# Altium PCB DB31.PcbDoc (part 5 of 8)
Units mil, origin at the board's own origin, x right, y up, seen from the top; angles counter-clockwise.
Board outline 3236.22 x 4456.69 mil, 8 copper layers (Top Layer, MidLayer1, MidLayer2, GND-Layer5, MidLayer3, VCC, MidLayer4, Bottom Layer), stack 61.8 mil thick; 226 components, 469 nets, 1815 pads, 1562 vias.
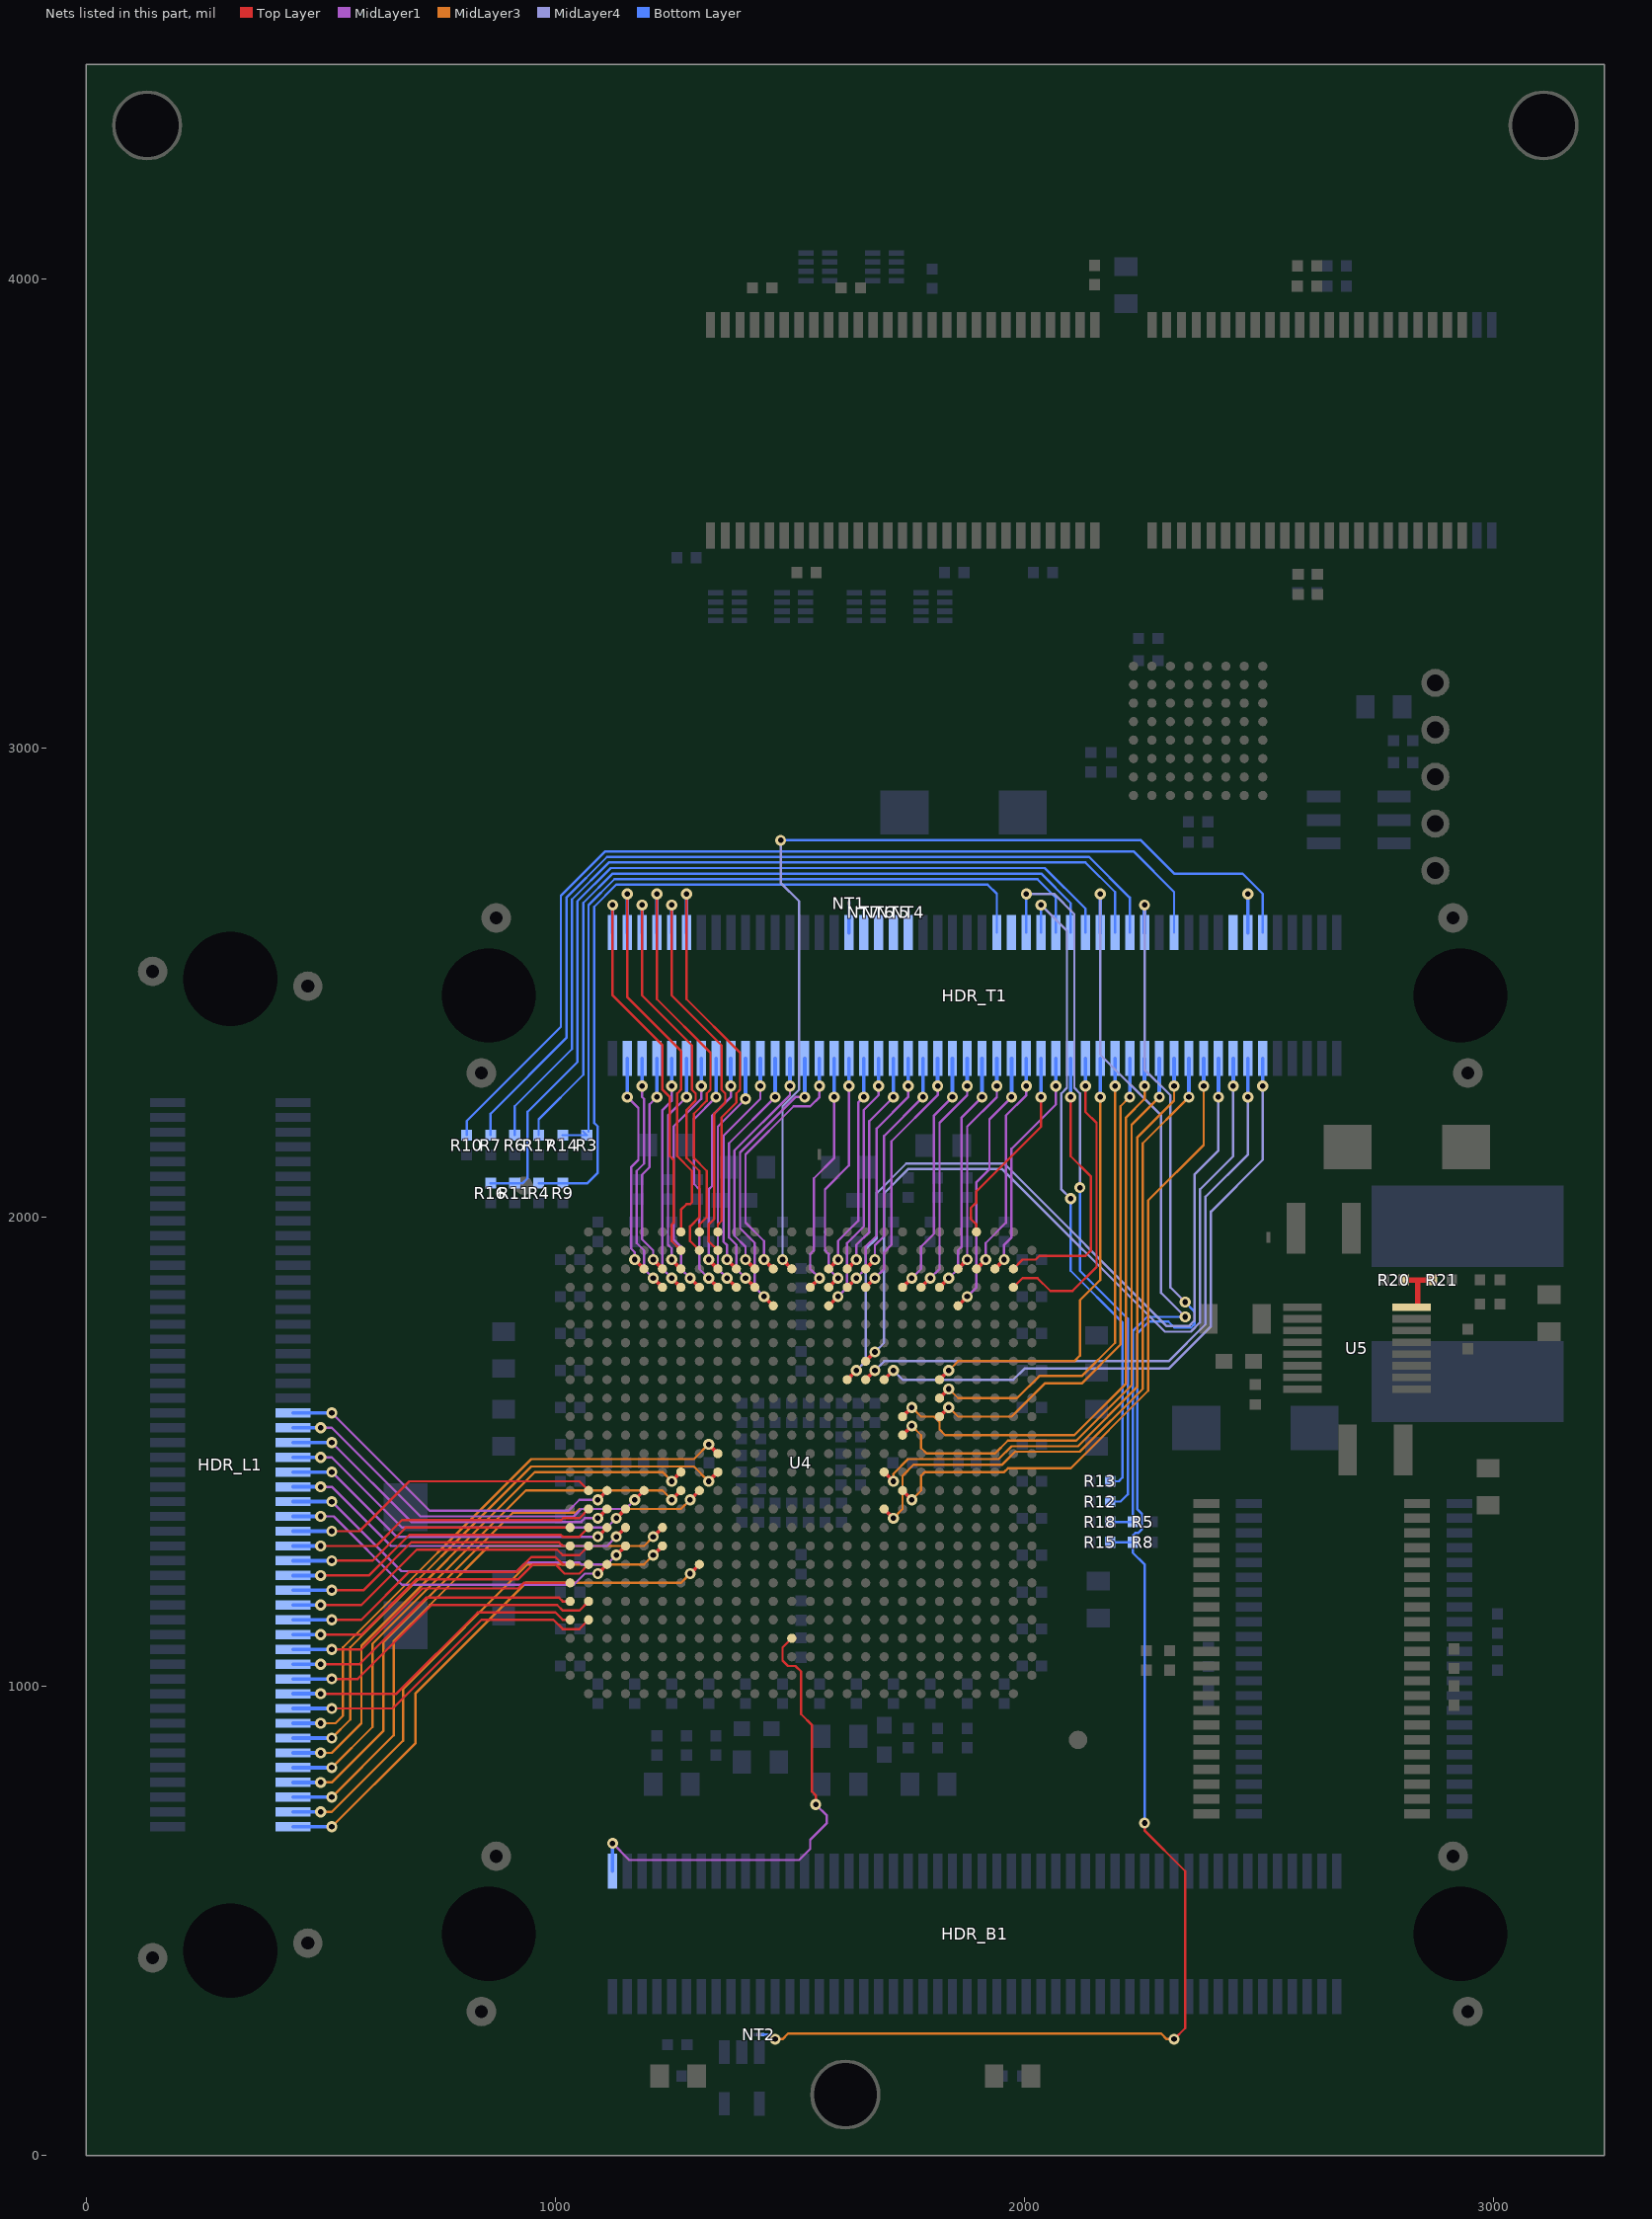
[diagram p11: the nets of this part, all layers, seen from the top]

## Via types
v1: diameter 23.62, hole 11.81, Top Layer to Bottom Layer, 947 vias
v2: diameter 23.62, hole 11.81, Top Layer to Bottom Layer, tented both sides, 476 vias
v3: diameter 27.56, hole 15.75, Top Layer to Bottom Layer, 138 vias
v4: diameter 23.62, hole 11.81, Top Layer to Bottom Layer, tented top, 1 vias

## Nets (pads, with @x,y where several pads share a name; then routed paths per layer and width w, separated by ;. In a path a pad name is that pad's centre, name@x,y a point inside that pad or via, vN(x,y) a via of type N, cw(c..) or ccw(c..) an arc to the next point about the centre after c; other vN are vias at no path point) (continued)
EXTEND_B21: HDR_L1.44 U4.R3 | length 773.7
  Top Layer w7.87: v1(1090.55,1397.64) U4.R3@1110.24,1417.32
  MidLayer1 w5: v2(523.62,1582.68) 732.28,1374.02 956.69,1374.02 968.5,1374.02 1027.56,1374.02 1051.18,1397.64 v1(1090.55,1397.64)
  Bottom Layer w7.87: HDR_L1.44@440.94,1582.67 v2(523.62,1582.68)
EXTEND_B22: HDR_L1.46 U4.R5 | length 849.1
  Top Layer w7.87: v1(1169.29,1397.64) U4.R5@1188.98,1417.32
  MidLayer1 w5: v2(500,1551.18) 523.62,1551.18 712.6,1362.2 956.69,1362.2 968.5,1362.2 1039.37,1362.2 1055.12,1377.95 1149.61,1377.95 v1(1169.29,1397.64)
  Bottom Layer w7.87: HDR_L1.46@440.94,1551.18 v2(500,1551.18)
EXTEND_B23: HDR_L1.48 U4.T3 | length 750.8
  Top Layer w7.87: v1(1090.55,1358.27) U4.T3@1110.24,1377.95
  MidLayer1 w5: v2(523.62,1519.68) 692.91,1350.39 956.69,1350.39 968.5,1350.39 1055.12,1350.39 1062.99,1358.27 v1(1090.55,1358.27)
  Bottom Layer w7.87: HDR_L1.48@440.94,1519.68 v2(523.62,1519.68)
EXTEND_B24: HDR_L1.50 U4.T4 | length 786.9
  Top Layer w7.87: v1(1129.92,1358.27) U4.T4@1149.61,1377.95
  MidLayer1 w5: v2(500,1488.19) 523.62,1488.19 673.23,1338.58 956.69,1338.58 968.5,1338.58 1110.24,1338.58 v1(1129.92,1358.27)
  Bottom Layer w7.87: HDR_L1.50@440.94,1488.19 v2(500,1488.19)
EXTEND_B25: HDR_L1.52 U4.U3 | length 734.5
  Top Layer w7.87: v1(1090.55,1318.9) U4.U3@1110.24,1338.58
  MidLayer1 w5: v2(523.62,1456.69) 661.42,1318.9 956.69,1318.9 968.5,1318.9 v1(1090.55,1318.9)
  Bottom Layer w7.87: HDR_L1.52@440.94,1456.69 v2(523.62,1456.69)
EXTEND_B26: HDR_L1.54 U4.U4 | length 777.2
  Top Layer w7.87: v1(1129.92,1318.9) U4.U4@1149.61,1338.58
  MidLayer1 w5: v2(500,1425.2) 523.62,1425.2 649.61,1299.21 956.69,1299.21 968.5,1299.21 1110.24,1299.21 v1(1129.92,1318.9)
  Bottom Layer w7.87: HDR_L1.54@440.94,1425.19 v2(500,1425.2)
EXTEND_B27: HDR_L1.56 U4.V4 | length 795.7
  Top Layer w7.87: v1(1129.92,1279.53) U4.V4@1149.61,1299.21
  MidLayer1 w5: v2(523.62,1393.7) 672,1245.32 918.55,1245.32 937.01,1263.78 956.69,1263.78 968.5,1263.78 1051.18,1263.78 1055.12,1259.84 1110.24,1259.84 v1(1129.92,1279.53)
  Bottom Layer w7.87: HDR_L1.56@440.94,1393.7 v2(523.62,1393.7)
EXTEND_B28: HDR_L1.58 U4.W3 | length 747.6
  Top Layer w7.87: v1(1090.55,1240.16) U4.W3@1110.24,1259.84
  MidLayer1 w5: v2(500,1362.21) 527.56,1362.21 673.23,1216.54 956.69,1216.54 968.5,1216.53 1039.37,1216.53 1062.99,1240.16 v1(1090.55,1240.16)
  Bottom Layer w7.87: HDR_L1.58@440.94,1362.2 v2(500,1362.21)
EXTEND_B29: HDR_L1.60 U4.R2 | length 682.1
  Top Layer w5: v2(523.62,1330.71) 582.68,1330.71 688.98,1437.01 956.69,1437.01 968.5,1437.01 1051.18,1437.01 U4.R2@1070.87,1417.32
  Bottom Layer w7.87: HDR_L1.60@440.94,1330.71 v2(523.62,1330.71)
EXTEND_B30: HDR_L1.62 U4.T2 | length 662.5
  Top Layer w5: v2(500,1299.21) 618.11,1299.21 673.23,1354.33 956.69,1354.33 968.5,1354.33 1012.8,1354.33 1016.73,1358.27 1051.18,1358.27 U4.T2@1070.87,1377.95
  Bottom Layer w7.87: HDR_L1.62@440.94,1299.21 v2(500,1299.21)
EXTEND_B31: HDR_L1.64 U4.U1 | length 619.9
  Top Layer w5: v2(523.62,1267.72) 610.24,1267.72 681.1,1338.58 956.69,1338.58 968.5,1338.58 U4.U1@1031.5,1338.58
  Bottom Layer w7.87: HDR_L1.64@440.94,1267.71 v2(523.62,1267.72)
EXTEND_B32: HDR_L1.66 U4.U2 | length 675.6
  Top Layer w5: v2(500,1236.22) 602.36,1236.22 688.98,1322.83 956.69,1322.83 968.5,1322.83 1011.81,1322.83 1015.75,1318.9 1051.18,1318.9 U4.U2@1070.87,1338.58
  Bottom Layer w7.87: HDR_L1.66@440.94,1236.22 v2(500,1236.22)
EXTEND_B33: HDR_L1.68 U4.V1 | length 636.2
  Top Layer w5: v2(523.62,1204.72) 590.55,1204.72 692.91,1307.09 956.69,1307.09 968.5,1307.09 1007.88,1307.09 1015.75,1299.21 U4.V1@1031.5,1299.21
  Bottom Layer w7.87: HDR_L1.68@440.94,1204.72 v2(523.62,1204.72)
EXTEND_B34: HDR_L1.70 U4.V2 | length 691.9
  Top Layer w5: v2(500,1173.23) 586.61,1173.23 704.72,1291.34 956.69,1291.34 968.5,1291.34 1003.94,1291.34 1015.75,1279.53 1051.18,1279.53 U4.V2@1070.87,1299.21
  Bottom Layer w7.87: HDR_L1.70@440.94,1173.23 v2(500,1173.23)
EXTEND_B35: HDR_L1.72 U4.W1 | length 652.5
  Top Layer w5: v2(523.62,1141.73) 586.61,1141.73 688.98,1244.1 917.32,1244.1 948.82,1275.59 956.69,1275.59 968.5,1275.59 1000,1275.59 1015.75,1259.84 U4.W1@1031.5,1259.84
  Bottom Layer w7.87: HDR_L1.72@440.94,1141.73 v2(523.62,1141.73)
EXTEND_B36: HDR_L1.74 U4.W2 | length 708.2
  Top Layer w5: v2(500,1110.24) 586.62,1110.24 704.72,1228.35 921.26,1228.35 952.76,1259.84 956.69,1259.84 968.5,1259.84 1000,1259.84 1019.68,1240.16 1051.18,1240.16 U4.W2@1070.87,1259.84
  Bottom Layer w7.87: HDR_L1.74@440.94,1110.23 v2(500,1110.24)
EXTEND_B37: HDR_L1.76 U4.Y1 | length 649.3
  Top Layer w5: v2(523.62,1078.74) 586.61,1078.74 716.54,1208.66 921.26,1208.66 933.07,1220.47 956.69,1220.47 968.5,1220.47 U4.Y1@1031.5,1220.47
  Bottom Layer w7.87: HDR_L1.76@440.94,1078.74 v2(523.62,1078.74)
EXTEND_B38: HDR_L1.78 U4.AA1 | length 652.5
  Top Layer w5: v2(500,1047.25) 582.68,1047.25 724.41,1188.98 956.69,1188.98 968.5,1188.98 1007.87,1188.98 1015.75,1181.1 U4.AA1@1031.5,1181.1
  Bottom Layer w7.87: HDR_L1.78@440.94,1047.24 v2(500,1047.25)
EXTEND_B39: HDR_L1.80 U4.AA2 | length 708.2
  Top Layer w5: v2(523.62,1015.75) 578.74,1015.75 736.22,1173.23 956.69,1173.23 968.5,1173.23 1003.94,1173.23 1015.75,1161.42 1051.18,1161.42 U4.AA2@1070.87,1181.1
  Bottom Layer w7.87: HDR_L1.80@440.94,1015.74 v2(523.62,1015.75)
EXTEND_B40: HDR_L1.82 U4.AB1 | length 668.8
  Top Layer w5: v2(500,984.25) 661.42,984.25 834.65,1157.48 956.69,1157.48 968.5,1157.48 1000,1157.48 1015.75,1141.73 U4.AB1@1031.5,1141.73
  Bottom Layer w7.87: HDR_L1.82@440.94,984.25 v2(500,984.25)
EXTEND_B41: HDR_L1.84 U4.AB2 | length 724.5
  Top Layer w5: v2(523.62,952.75) 653.54,952.75 842.52,1141.73 956.69,1141.73 968.5,1141.73 996.06,1141.73 1015.75,1122.05 1051.18,1122.05 U4.AB2@1070.87,1141.73
  Bottom Layer w7.87: HDR_L1.84@440.94,952.75 v2(523.62,952.75)
EXTEND_B42: HDR_L1.86 U4.N9 | length 1245.2
  Top Layer w7.87: v1(1326.77,1515.75) U4.N9@1346.46,1496.06
  MidLayer3 w5: v2(500,921.26) 531.5,921.26 547.24,937.01 547.24,1082.68 948.82,1484.25 956.69,1484.25 968.51,1484.25 1295.28,1484.25 v1(1326.77,1515.75)
  Bottom Layer w7.87: HDR_L1.86@440.94,921.26 v2(500,921.26)
EXTEND_B43: HDR_L1.88 U4.P9 | length 1256.4
  Top Layer w7.87: v1(1326.77,1437.01) U4.P9@1346.46,1456.69
  MidLayer3 w5: v2(523.62,889.76) 562.99,929.13 562.99,1082.68 948.82,1468.5 956.69,1468.5 968.51,1468.5 1295.27,1468.5 v1(1326.77,1437.01)
  Bottom Layer w7.87: HDR_L1.88@440.94,889.76 v2(523.62,889.76)
EXTEND_B44: HDR_L1.90 U4.P7 | length 1187.8
  Top Layer w7.87: v1(1248.03,1437.01) U4.P7@1267.72,1456.69
  MidLayer3 w5: v2(500,858.27) 523.62,858.27 586.61,921.26 586.61,1086.61 956.69,1456.69 968.51,1456.69 1228.35,1456.69 v1(1248.03,1437.01)
  Bottom Layer w7.87: HDR_L1.90@440.94,858.26 v2(500,858.27)
EXTEND_B45: HDR_L1.92 U4.R7 | length 1191.5
  Top Layer w7.87: v1(1248.03,1397.64) U4.R7@1267.72,1417.32
  MidLayer3 w5: v2(523.62,826.77) 610.24,913.38 610.24,1090.55 937.01,1417.32 956.69,1417.32 968.51,1417.32 1228.35,1417.32 v1(1248.03,1397.64)
  Bottom Layer w7.87: HDR_L1.92@440.94,826.77 v2(523.62,826.77)
EXTEND_B46: HDR_L1.94 U4.R8 | length 1234.5
  Top Layer w7.87: v1(1287.4,1397.64) U4.R8@1307.09,1417.32
  MidLayer3 w5: v2(500,795.28) 523.62,795.28 633.86,905.51 633.86,1094.49 909.45,1370.08 956.69,1370.08 968.51,1370.08 1043.3,1370.08 1051.18,1377.95 1192.91,1377.95 1267.72,1377.95 v1(1287.4,1397.64)
  Bottom Layer w7.87: HDR_L1.94@440.94,795.27 v2(500,795.28)
EXTEND_B47: HDR_L1.96 U4.U6 | length 1143.1
  Top Layer w7.87: v1(1208.66,1318.9) U4.U6@1228.35,1338.58
  MidLayer3 w5: v2(523.62,763.78) 655.23,895.39 655.23,1096.17 732.28,1173.23 858.27,1299.21 956.69,1299.21 968.51,1299.22 1188.98,1299.21 v1(1208.66,1318.9)
  Bottom Layer w7.87: HDR_L1.96@440.95,763.78 v2(523.62,763.78)
EXTEND_B48: HDR_L1.98 U4.V6 | length 1086.8
  Top Layer w7.87: v1(1208.66,1279.53) U4.V6@1228.35,1299.21
  MidLayer3 w5: v2(500,732.28) 523.62,732.28 675.28,883.94 675.28,994.17 940.94,1259.84 956.69,1259.84 968.51,1259.84 1188.98,1259.84 v1(1208.66,1279.53)
  Bottom Layer w7.87: HDR_L1.98@440.94,732.28 v2(500,732.28)
EXTEND_B49: HDR_L1.100 U4.W8 | length 1160
  Top Layer w7.87: v1(1287.4,1240.16) U4.W8@1307.09,1259.84
  MidLayer3 w5: v2(523.62,700.79) 702.1,879.26 702.1,985.56 937.01,1220.47 956.69,1220.47 968.51,1220.47 1267.72,1220.47 v1(1287.4,1240.16)
  Bottom Layer w7.87: HDR_L1.100@440.94,700.78 v2(523.62,700.79)
EXTEND_C0: HDR_T1.89 U4.J18 | length 1436
  Top Layer w7.87: U4.J18@1700.79,1653.54 v1(1720.47,1673.23)
  MidLayer4 w5: v1(1720.47,1673.23) 1740.16,1653.54 1976.38,1653.54 2000,1677.16 2078.74,1677.16 2090.55,1677.17 2307.09,1677.17 2397.64,1767.72 2397.64,2011.81 2507.87,2122.05 v2(2507.87,2279.53)
  Bottom Layer w7.87: v2(2507.87,2279.53) HDR_T1.89@2507.88,2338.58 v2(2507.87,2279.53)
EXTEND_C1: HDR_T1.87 U4.J17 | length 1377.8
  Top Layer w7.87: U4.J17@1661.42,1653.54 v1(1681.1,1673.23)
  MidLayer4 w5: v1(1681.1,1673.23) 1700.79,1692.91 2078.74,1692.91 2090.55,1692.91 2307.09,1692.91 2385.83,1771.65 2385.83,2043.31 2476.38,2133.86 v2(2476.38,2255.9)
  Bottom Layer w7.87: v2(2476.38,2255.9) HDR_T1.87@2476.38,2338.58
EXTEND_C2: HDR_T1.85 U4.H17 | length 1813
  Top Layer w7.87: U4.H17@1661.42,1692.91 v1(1681.1,1712.6)
  MidLayer4 w5: v1(1681.1,1712.6) 1700.79,1732.28 1700.79,2031.5 1700.79,2042.32 1700.79,2051.18 1751.97,2102.36 1952.76,2102.36 2299.21,1755.91 2354.33,1755.91 2374.02,1775.59 2374.02,2059.06 2444.88,2129.92 v2(2444.88,2279.53)
  Bottom Layer w7.87: v2(2444.88,2279.53) HDR_T1.85@2444.88,2338.58
EXTEND_C3: HDR_T1.83 U4.J16 | length 1855.6
  Top Layer w7.87: U4.J16@1622.05,1653.54 v1(1641.73,1673.23)
  MidLayer4 w5: v1(1641.73,1673.23) 1661.42,1692.91 1661.42,1931.1 1685.04,1954.72 1685.04,2031.5 1685.04,2042.32 1685.04,2051.18 1748.03,2114.17 1956.69,2114.17 2303.15,1767.72 2350.39,1767.72 2362.2,1779.53 2362.2,2090.55 2413.38,2141.73 v2(2413.38,2255.9)
  Bottom Layer w7.87: v2(2413.38,2255.9) HDR_T1.83@2413.39,2338.58
EXTEND_C4: HDR_T1.81 U4.R19 | length 1404.1
  Top Layer w7.87: U4.R19@1740.16,1417.32 v1(1759.84,1397.64)
  MidLayer3 w5: v1@1760.03,1397.46 1779.89,1417.32 1779.89,1449.18 1787.4,1456.69 1956.69,1456.69 1964.57,1464.57 2078.74,1464.57 2090.55,1464.57 2098.43,1464.57 2263.78,1629.92 2263.78,2035.43 2381.89,2153.54 v2(2381.89,2279.53)
  Bottom Layer w7.87: v2(2381.89,2279.53) HDR_T1.81@2381.89,2338.58
EXTEND_C5: HDR_T1.79 U4.T18 | length 1460.5
  Top Layer w7.87: U4.T18@1700.79,1377.95 v1(1720.47,1358.27)
  MidLayer3 w5: v1(1720.47,1358.27) 1740.16,1377.95 1740.16,1448.82 1763.78,1472.44 1952.76,1472.44 1980.32,1500 2078.74,1500 2090.55,1500 2118.11,1500 2251.97,1633.86 2251.97,2157.48 v2(2350.39,2255.9)
  Bottom Layer w7.87: v2(2350.39,2255.9) HDR_T1.79@2350.4,2338.58
EXTEND_C6: HDR_T1.77 U4.P18 | length 1373.3
  Top Layer w7.87: U4.P18@1700.79,1456.69 v1(1720.47,1437.01)
  MidLayer3 w5: v1(1720.47,1437.01) 1720.48,1452.76 1751.97,1484.25 1944.88,1484.25 1972.44,1511.81 2078.74,1511.81 2090.55,1511.81 2114.17,1511.81 2240.16,1637.8 2240.16,2169.29 2318.89,2248.03 v2(2318.89,2279.53)
  Bottom Layer w7.87: v2(2318.89,2279.53) HDR_T1.77@2318.9,2338.58
EXTEND_C7: HDR_T1.75 U4.M19 | length 1318.6
  Top Layer w7.87: U4.M19@1740.16,1535.43 v1(1759.84,1555.12)
  MidLayer3 w5: v1(1759.84,1555.12) 1779.53,1535.44 1779.53,1507.87 1791.34,1496.06 1937.01,1496.06 1964.57,1523.62 2078.74,1523.62 2090.55,1523.62 2110.24,1523.62 2228.35,1641.73 2228.35,2196.85 v2(2287.4,2255.9)
  Bottom Layer w7.87: v2(2287.4,2255.9) HDR_T1.75@2287.4,2338.58
EXTEND_C8: HDR_T1.73 U4.L19 | length 1273.1
  Top Layer w7.87: U4.L19@1740.16,1574.8 v1(1759.84,1594.49)
  MidLayer3 w5: v1(1759.84,1594.49) 1779.53,1574.8 1807.09,1574.8 1818.9,1562.99 1818.9,1547.24 1830.71,1535.43 2078.74,1535.43 2090.55,1535.43 2106.3,1535.43 2216.54,1645.67 2216.54,2212.6 2255.9,2251.97 v2(2255.9,2279.53)
  Bottom Layer w7.87: v2(2255.9,2279.53) HDR_T1.73@2255.91,2338.58
EXTEND_C9: HDR_T1.71 U4.L21 | length 1084.1
  Top Layer w7.87: U4.L21@1818.9,1574.8 v1(1838.59,1594.49)
  MidLayer3 w5: v1(1838.59,1594.49) 1858.27,1574.8 1972.44,1574.8 2043.31,1645.67 2078.74,1645.67 2090.55,1645.67 2122.05,1645.67 2204.72,1728.35 2204.72,2236.22 v2(2224.41,2255.9)
  Bottom Layer w7.87: v2(2224.41,2255.9) HDR_T1.71@2224.41,2338.58
EXTEND_C10: HDR_T1.69 U4.K21 | length 1045.5
  Top Layer w7.87: U4.K21@1818.9,1614.17 v1(1838.59,1633.86)
  MidLayer3 w5: v1(1838.59,1633.86) 1858.27,1614.17 1913.39,1614.17 1984.25,1614.17 2031.5,1661.42 2078.74,1661.42 2090.55,1661.42 2122.05,1661.42 2192.91,1732.28 v2(2192.91,2279.53)
  Bottom Layer w7.87: v2(2192.91,2279.53) HDR_T1.69@2192.91,2338.58
EXTEND_C11: HDR_T1.67 U4.J21 | length 972.2
  Top Layer w7.87: U4.J21@1818.9,1653.54 v1(1838.59,1673.23)
  MidLayer3 w5: v1(1838.59,1673.23) 1858.27,1692.91 2078.74,1692.91 2090.55,1692.91 2106.3,1692.91 2118.11,1704.72 2118.11,1822.83 2161.42,1866.14 v2(2161.42,2255.9)
  Bottom Layer w7.87: v2(2161.42,2255.9) HDR_T1.67@2161.42,2338.58
EXTEND_C12: HDR_T1.65 U4.D25 | length 672.6
  Top Layer w5: U4.D25@1976.38,1850.39 1996.06,1870.08 2027.56,1870.08 2055.12,1842.52 2078.74,1842.52 2090.55,1842.52 2102.36,1842.52 2153.54,1893.7 2153.54,2200.79 2129.92,2224.41 v2(2129.92,2279.53)
  Bottom Layer w7.87: v2(2129.92,2279.53) HDR_T1.65@2129.92,2338.58
EXTEND_C13: HDR_T1.63 U4.C25 | length 609
  Top Layer w5: U4.C25@1976.38,1889.76 1996.06,1909.45 2023.62,1909.45 2031.5,1917.32 2078.74,1917.32 2090.55,1917.32 2129.92,1917.32 2141.73,1929.13 2141.73,2086.61 2098.42,2129.92 v2(2098.42,2255.9)
  Bottom Layer w7.87: v2(2098.42,2255.9) HDR_T1.63@2098.43,2338.58
EXTEND_C14: HDR_T1.61 U4.C24 | length 502.6
  Top Layer w7.87: U4.C24@1937.01,1889.76 v1(1956.7,1909.45)
  MidLayer1 w5: v1(1956.7,1909.45) 1956.69,1940.95 1972.44,1956.69 1972.44,2031.5 1972.44,2039.37 1972.44,2145.67 2066.93,2240.16 v2(2066.93,2279.53)
  Bottom Layer w7.87: v2(2066.93,2279.53) HDR_T1.61@2066.93,2338.58
EXTEND_C15: HDR_T1.59 U4.A23 | length 436.9
  Top Layer w5: U4.A23@1897.64,1968.5 1897.64,1984.25 1885.83,1996.06 1885.83,2019.69 1897.64,2031.5 1897.64,2039.37 1897.64,2055.12 2035.43,2192.91 v2(2035.43,2255.9)
  Bottom Layer w7.87: v2(2035.43,2255.9) HDR_T1.59@2035.43,2338.58
EXTEND_C16: HDR_T1.57 U4.C23 | length 492.8
  Top Layer w7.87: U4.C23@1897.64,1889.76 v1(1917.33,1909.45)
  MidLayer1 w5: v1(1917.33,1909.45) 1917.32,1944.88 1960.63,1988.19 1960.63,2031.5 1960.63,2039.37 1960.63,2216.53 2003.94,2259.84 v2(2003.93,2279.53)
  Bottom Layer w7.87: v2(2003.93,2279.53) HDR_T1.57@2003.94,2338.58
EXTEND_C17: HDR_T1.55 U4.E22 | length 574.8
  Top Layer w7.87: U4.E22@1858.27,1811.02 v1(1877.95,1830.71)
  MidLayer1 w5: v1(1877.95,1830.71) 1897.64,1850.39 1897.64,2031.5 1897.64,2039.37 1897.64,2074.8 1925.2,2102.36 1925.2,2208.66 v2(1972.44,2255.9)
  Bottom Layer w7.87: v2(1972.44,2255.9) HDR_T1.55@1972.44,2338.58
EXTEND_C18: HDR_T1.53 U4.C22 | length 483.1
  Top Layer w7.87: U4.C22@1858.27,1889.76 v1(1877.95,1909.45)
  MidLayer1 w5: v1(1877.95,1909.45) 1877.95,2031.5 1877.95,2039.37 1877.95,2192.91 1940.94,2255.9 v2(1940.94,2279.53)
  Bottom Layer w7.87: v2(1940.94,2279.53) HDR_T1.53@1940.95,2338.58
EXTEND_C19: HDR_T1.51 U4.D21 | length 525.7
  Top Layer w7.87: U4.D21@1818.9,1850.39 v1(1838.59,1870.08)
  MidLayer1 w5: v1(1838.59,1870.08) 1858.27,1889.76 1858.27,1929.13 1866.14,1937.01 1866.14,2031.5 1866.14,2039.37 1866.14,2212.6 v2(1909.45,2255.9)
  Bottom Layer w7.87: v2(1909.45,2255.9) HDR_T1.51@1909.45,2338.58
EXTEND_C20: HDR_T1.49 U4.D20 | length 529
  Top Layer w7.87: U4.D20@1779.53,1850.39 v1(1799.22,1870.08)
  MidLayer1 w5: v1(1799.22,1870.08) 1818.9,1889.76 1818.9,2031.5 1818.9,2039.37 1818.9,2200.79 1877.95,2259.84 v2(1877.95,2279.53)
  Bottom Layer w7.87: v2(1877.95,2279.53) HDR_T1.49@1877.95,2338.58
EXTEND_C21: HDR_T1.47 U4.D19 | length 532.2
  Top Layer w7.87: U4.D19@1740.16,1850.39 v1(1759.84,1870.08)
  MidLayer1 w5: v1(1759.84,1870.08) 1779.53,1889.76 1779.53,1937.01 1807.09,1964.57 1807.09,2031.5 1807.09,2039.37 1807.09,2216.54 v2(1846.46,2255.9)
  Bottom Layer w7.87: v2(1846.46,2255.9) HDR_T1.47@1846.46,2338.58
EXTEND_C22: HDR_T1.45 U4.D17 | length 551.8
  Top Layer w7.87: U4.D17@1661.42,1850.39 v1(1681.1,1870.08)
  MidLayer1 w5: v1(1681.1,1870.08) 1700.79,1889.76 1700.79,1925.2 1716.54,1940.95 1716.54,2031.5 1716.54,2039.37 1716.54,2161.42 1814.96,2259.84 v2(1814.96,2279.53)
  Bottom Layer w7.87: v2(1814.96,2279.53) HDR_T1.45@1814.96,2338.58
EXTEND_C23: HDR_T1.43 U4.C17 | length 499.4
  Top Layer w7.87: U4.C17@1661.42,1889.76 v1(1681.1,1909.45)
  MidLayer1 w5: v1(1681.1,1909.45) 1681.1,1939.96 1700.79,1959.65 1700.79,2031.5 1700.79,2039.37 1700.79,2173.23 v2(1783.46,2255.9)
  Bottom Layer w7.87: v2(1783.46,2255.9) HDR_T1.43@1783.47,2338.58
EXTEND_C24: HDR_T1.41 U4.D16 | length 542
  Top Layer w7.87: U4.D16@1622.05,1850.39 v1(1641.73,1870.08)
  MidLayer1 w5: v1(1641.73,1870.08) 1661.42,1889.76 1661.42,1937.01 1685.04,1960.63 1685.04,2031.5 1685.04,2039.37 1685.04,2188.98 1751.97,2255.9 v2(1751.97,2279.53)
  Bottom Layer w7.87: v2(1751.97,2279.53) HDR_T1.41@1751.97,2338.58
EXTEND_C25: HDR_T1.39 U4.C16 | length 562
  Top Layer w7.87: U4.C16@1622.05,1889.76 v1(1641.73,1909.45)
  MidLayer1 w5: v1(1641.73,1909.45) 1641.73,1940.94 1669.29,1968.5 1669.29,2031.5 1669.29,2039.37 1669.29,2204.72 ; 1669.29,2204.72 v2(1720.47,2255.9) 1669.29,2204.72
  Bottom Layer w7.87: v2(1720.47,2255.9) HDR_T1.39@1720.47,2338.58
EXTEND_C26: HDR_T1.37 U4.E15 | length 571.6
  Top Layer w7.87: U4.E15@1582.68,1811.02 v1(1602.36,1830.71)
  MidLayer1 w5: v1(1602.36,1830.71) 1622.05,1850.39 1622.05,1944.88 1657.48,1980.31 1657.48,2031.5 1657.48,2039.37 1657.48,2228.35 1688.98,2259.84 v2(1688.97,2279.53)
  Bottom Layer w7.87: v2(1688.97,2279.53) HDR_T1.37@1688.98,2338.58
EXTEND_C27: HDR_T1.35 U4.C15 | length 479.8
  Top Layer w7.87: U4.C15@1582.68,1889.76 v1(1602.36,1909.45)
  MidLayer1 w5: v1(1602.36,1909.45) 1602.36,1948.82 1645.67,1992.13 1645.67,2031.5 1645.67,2039.37 1645.67,2244.09 v2(1657.48,2255.9)
  Bottom Layer w7.87: v2(1657.48,2255.9) HDR_T1.35@1657.48,2338.58
EXTEND_C28: HDR_T1.33 U4.D15 | length 529
  Top Layer w7.87: U4.D15@1582.68,1850.39 v1(1602.36,1870.08)
  MidLayer1 w5: v1(1602.36,1870.08) 1582.68,1889.77 1582.68,1921.26 1574.8,1929.13 1574.8,2031.5 1574.8,2039.37 1574.8,2059.06 1625.98,2110.23 v2(1625.98,2279.53)
  Bottom Layer w7.87: v2(1625.98,2279.53) HDR_T1.33@1625.99,2338.58
EXTEND_C29: HDR_T1.31 U4.D14 | length 525.7
  Top Layer w7.87: U4.D14@1543.31,1850.39 v1(1562.99,1870.08)
  MidLayer1 w5: v1(1562.99,1870.08) 1543.31,1889.77 1543.31,1921.26 1551.18,1929.13 1551.18,2031.5 1551.18,2039.37 1551.18,2082.68 1594.49,2125.98 v2(1594.49,2255.9)
  Bottom Layer w7.87: v2(1594.49,2255.9) HDR_T1.31@1594.49,2338.58
EXTEND_C30: HDR_T1.29 U4.C12 | length 559.3
  Top Layer w7.87: v1(1444.88,1909.45) U4.C12@1464.57,1889.76
  MidLayer1 w5: v1(1444.88,1909.45) 1444.88,1948.82 1405.51,1988.19 1405.51,2031.5 1405.51,2039.37 1405.51,2133.86 1507.87,2236.22 1543.31,2236.22 1562.99,2255.9 v2(1562.99,2279.53)
  Bottom Layer w7.87: v2(1562.99,2279.53) HDR_T1.29@1562.99,2338.58
EXTEND_C31: HDR_T1.27 U4.E12 | length 625.5
  Top Layer w7.87: v1(1444.88,1830.71) U4.E12@1464.57,1811.02
  MidLayer1 w5: v1(1444.88,1830.71) 1425.2,1850.39 1425.2,1944.88 1393.7,1976.38 1393.7,2031.5 1393.7,2039.37 1393.7,2137.8 1511.81,2255.9 v2(1531.5,2255.9)
  Bottom Layer w7.87: v2(1531.5,2255.9) HDR_T1.27@1531.5,2338.58
EXTEND_C32: HDR_T1.25 U4.C11 | length 515.7
  Top Layer w7.87: v1(1405.51,1909.45) U4.C11@1425.2,1889.76
  MidLayer1 w5: v1(1405.51,1909.45) 1405.51,1937.01 1381.89,1960.63 1381.89,2031.5 1381.89,2039.37 1381.89,2141.73 1500,2259.84 v2(1500,2279.53)
  Bottom Layer w7.87: v2(1500,2279.53) HDR_T1.25@1500,2338.58
EXTEND_C33: HDR_T1.23 U4.D11 | length 551.8
  Top Layer w7.87: v1(1405.51,1870.08) U4.D11@1425.2,1850.39
  MidLayer1 w5: v1(1405.51,1870.08) 1385.83,1889.76 1385.83,1940.94 1370.08,1956.69 1370.08,2031.5 1370.08,2039.37 1370.08,2157.48 v2(1468.5,2255.9)
  Bottom Layer w7.87: v2(1468.5,2255.9) HDR_T1.23@1468.5,2338.58
EXTEND_C34: HDR_T1.21 U4.C10 | length 492.9
  Top Layer w7.87: v1(1366.14,1909.45) U4.C10@1385.83,1889.76
  MidLayer1 w5: v1(1366.14,1909.45) 1366.14,1939.96 1358.27,1947.83 1358.27,2031.5 1358.27,2039.37 1358.27,2173.23 1437.01,2251.97 v2(1437.01,2279.53)
  Bottom Layer w7.87: v2(1437.01,2279.53) HDR_T1.21@1437.01,2338.58
EXTEND_C35: HDR_T1.19 U4.D10 | length 525
  Top Layer w7.87: v1(1366.14,1870.08) U4.D10@1385.83,1850.39
  MidLayer1 w5: v1(1366.14,1870.08) 1346.46,1889.76 1346.46,2031.5 1346.46,2039.37 1346.46,2192.91 v2(1405.51,2251.97)
  Bottom Layer w7.87: v2@1405.51,2255.9 HDR_T1.19@1405.51,2338.58
EXTEND_C36: HDR_T1.17 U4.C9 | length 476.5
  Top Layer w7.87: v1(1326.77,1909.45) U4.C9@1346.46,1889.76
  MidLayer1 w5: v1(1326.77,1909.45) 1326.77,2031.49 1326.77,2039.37 1326.77,2059.05 1334.65,2066.93 1334.65,2216.54 1374.02,2255.91 v2(1374.02,2279.53)
  Bottom Layer w7.87: v2(1374.02,2279.53) HDR_T1.17@1374.02,2338.58
EXTEND_C37: HDR_T1.15 U4.D9 | length 529
  Top Layer w7.87: v1(1326.77,1870.08) U4.D9@1346.46,1850.39
  MidLayer1 w5: v1(1326.77,1870.08) 1307.09,1889.76 1307.09,2031.5 1307.09,2039.37 1307.09,2059.06 1295.28,2070.87 1295.28,2208.66 v2(1342.52,2255.9)
  Bottom Layer w7.87: v2(1342.52,2255.9) HDR_T1.15@1342.52,2338.58
EXTEND_C38: HDR_T1.13 U4.D8 | length 535.5
  Top Layer w7.87: v1(1287.4,1870.08) U4.D8@1307.09,1850.39
  MidLayer1 w5: v1(1287.4,1870.08) 1267.72,1889.76 1267.72,1937.01 1251.97,1952.76 1251.97,2031.5 1251.97,2039.37 1251.97,2192.91 1311.02,2251.97 v2(1311.02,2279.53)
  Bottom Layer w7.87: v2(1311.02,2279.53) HDR_T1.13@1311.02,2338.58
EXTEND_C39: HDR_T1.11 U4.C7 | length 476.5
  Top Layer w7.87: v1(1248.03,1909.45) U4.C7@1267.72,1889.76
  MidLayer1 w5: v1(1248.03,1909.45) 1248.03,1933.07 1240.16,1940.94 1240.16,2031.5 1240.16,2039.37 1240.16,2216.53 v2(1279.53,2255.9)
  Bottom Layer w7.87: v2(1279.53,2255.9) HDR_T1.11@1279.53,2338.58
EXTEND_C40: HDR_T1.12 U4.A9 | length 870
  Top Layer w5: v2(1279.53,2688.98) 1279.53,2464.57 1393.7,2350.39 1393.7,2271.65 1385.83,2263.78 1385.83,2244.09 1354.33,2212.6 1354.33,2043.31 1354.33,2031.5 1354.33,1992.13 1346.46,1984.25 U4.A9@1346.46,1968.5
  Bottom Layer w7.87: HDR_T1.12@1279.53,2606.3 v2(1279.53,2688.98)
EXTEND_C41: HDR_T1.9 U4.D7 | length 512.6
  Top Layer w7.87: v1(1248.03,1870.08) U4.D7@1267.72,1850.39
  MidLayer1 w5: v1(1248.03,1870.08) 1228.35,1889.76 1228.35,2031.5 1228.35,2039.37 1228.35,2228.35 1248.03,2248.03 v2(1248.03,2279.53)
  Bottom Layer w7.87: v2(1248.03,2279.53) HDR_T1.9@1248.03,2338.58
EXTEND_C42: HDR_T1.10 U4.B9 | length 865.4
  Top Layer w5: v2(1248.03,2665.35) 1248.03,2472.44 1354.33,2366.14 1354.33,2271.65 1362.2,2263.78 1362.2,2244.09 1338.58,2220.47 1338.58,2043.31 1338.58,2031.5 1338.58,1996.06 1326.77,1984.25 1326.77,1948.82 U4.B9@1346.46,1929.13
  Bottom Layer w7.87: HDR_T1.10@1248.03,2606.3 v2(1248.03,2665.35)
EXTEND_C43: HDR_T1.7 U4.C6 | length 479.8
  Top Layer w7.87: v1(1208.66,1909.45) U4.C6@1228.35,1889.76
  MidLayer1 w5: v1(1208.66,1909.45) 1208.66,1929.13 1185.04,1952.75 1185.04,2031.5 1185.04,2039.37 1185.04,2090.55 1200.79,2106.3 1200.79,2240.16 v2(1216.54,2255.9)
  Bottom Layer w7.87: v2(1216.54,2255.9) HDR_T1.7@1216.54,2338.58
EXTEND_C44: HDR_T1.8 U4.A8 | length 883.1
  Top Layer w5: v2(1216.54,2688.98) 1216.54,2464.57 1330.71,2350.39 1330.71,2271.65 1322.83,2263.78 1322.83,2248.03 1295.28,2220.47 1295.28,2125.98 1322.83,2098.43 1322.83,2043.31 1322.83,2031.5 1322.83,2000 1307.09,1984.25 U4.A8@1307.09,1968.5
  Bottom Layer w7.87: HDR_T1.8@1216.54,2606.3 v2(1216.54,2688.98)
EXTEND_C45: HDR_T1.5 U4.D6 | length 519.2
  Top Layer w7.87: v1(1208.66,1870.08) U4.D6@1228.35,1850.39
  MidLayer1 w5: v2(1185.04,2279.53) 1185.04,2255.91 1188.98,2251.97 1188.98,2114.17 1173.23,2098.43 1173.23,2039.37 1173.23,2031.5 1173.23,1944.88 1188.98,1929.13 1188.98,1889.76 v1(1208.66,1870.08)
  Bottom Layer w7.87: v2(1185.04,2279.53) HDR_T1.5@1185.04,2338.58
EXTEND_C46: HDR_T1.6 U4.B8 | length 937.5
  Top Layer w5: v2(1185.04,2665.35) 1185.04,2472.44 1291.34,2366.14 1291.34,2271.65 1299.21,2263.78 1299.21,2248.03 1279.53,2228.35 1279.53,2125.98 1307.09,2098.43 1307.09,2043.31 1307.09,2031.5 1307.09,2000 1287.4,1980.32 1287.4,1948.82 U4.B8@1307.09,1929.13
  Bottom Layer w7.87: HDR_T1.6@1185.04,2606.3 v2(1185.04,2665.35) HDR_T1.6@1185.04,2606.3
EXTEND_C47: HDR_T1.3 U4.C5 | length 476.5
  Top Layer w7.87: v1(1169.29,1909.45) U4.C5@1188.98,1889.76
  MidLayer1 w5: v2(1153.54,2255.9) 1177.17,2232.28 1177.17,2122.05 1161.42,2106.3 1161.42,2039.37 1161.42,2031.5 1161.42,1933.07 1169.29,1925.2 v1(1169.29,1909.45)
  Bottom Layer w7.87: v2(1153.54,2255.9) HDR_T1.3@1153.54,2338.58
EXTEND_C48: HDR_T1.4 U4.A7 | length 940.2
  Top Layer w5: v2(1153.54,2688.98) 1153.54,2468.5 1267.72,2354.33 1267.72,2271.65 1259.84,2263.78 1259.84,2129.92 1291.34,2098.43 1291.34,2043.31 1291.34,2031.5 1287.4,2027.56 1279.53,2027.56 1267.72,2015.75 U4.A7@1267.72,1968.5
  Bottom Layer w7.87: 1153.54,2665.35 HDR_T1.4@1153.54,2606.3 v2(1153.54,2688.98)
EXTEND_C49: HDR_T1.2 U4.B7 | length 858.9
  Top Layer w5: v2(1122.05,2665.35) 1122.05,2472.44 1228.35,2366.14 1228.35,2271.65 1244.09,2255.91 1244.09,2129.92 1251.97,2122.05 1251.97,2043.31 1251.97,2031.5 1251.97,1988.19 1248.03,1984.25 1248.03,1948.82 U4.B7@1267.72,1929.13
  Bottom Layer w7.87: HDR_T1.2@1122.05,2606.3 v2(1122.05,2665.35)
FB: R20.2 R21.1 U5.8 | length 120.2
  Top Layer w7.87: U5.8@2842.51,1807.09 U5.8@2842.51,1808.25
  Top Layer w11.81: R20.2@2808.58,1866.14 2838.58,1866.14 ; U5.8@2838.58,1807.09 2838.58,1808.25 2838.58,1866.14 ; R21.1@2868.58,1866.14 2838.58,1866.14
FPGA_CCLK: HDR_T1.66 R11.1 R16.1 | length 1916.7
  Bottom Layer w5: R16.1@862.2,2072.36 R11.1@913.38,2072.36 930.63,2072.36 940.94,2082.68 940.94,2224.41 1047.24,2330.71 1047.24,2673.23 1118.11,2744.09 2043.31,2744.09 2129.92,2657.48 HDR_T1.66@2129.92,2606.3
FPGA_CLK: HDR_B1.2 U4.AC13 | length 1024.8
  Top Layer w5: U4.AC13@1503.94,1102.36 1484.25,1082.68 1484.25,1055.12 1496.06,1043.31 1511.81,1043.31 1523.62,1031.5 1523.62,940.95 1547.24,917.32 1547.24,775.59 1555.12,767.72 v1(1555.12,748.03)
  MidLayer1 w5: v2(1122.05,665.35) 1157.48,629.92 1519.69,629.92 1543.31,653.54 1543.31,673.23 1578.74,708.66 1578.74,724.41 v1(1555.12,748.03)
  Bottom Layer w7.87: HDR_B1.2@1122.05,606.3 v2(1122.05,665.35)
FPGA_CLK1: HDR_T1.90 U4.C13 | length 2110.1
  Top Layer w7.87: v1(1484.25,1909.45) U4.C13@1503.94,1889.76
  MidLayer4 w5: v1(1480.31,2803.15) 1480.31,2712.6 1519.68,2673.23 1519.68,2271.65 1484.25,2236.22 v1(1484.25,1909.45)
  Bottom Layer w5: v1(1480.31,2803.15) 2248.03,2803.15 2318.9,2732.28 2464.57,2732.28 2507.87,2688.98 HDR_T1.90@2507.88,2606.3
FPGA_DIN: HDR_T1.64 R17.1 | length 1688.3
  Bottom Layer w5: R17.1@964.56,2174.72 964.56,2208.66 1059.55,2303.64 1059.55,2669.79 1122.04,2732.28 2035.43,2732.28 2098.43,2669.29 HDR_T1.64@2098.43,2606.3
FPGA_DONE: HDR_T1.74 NT2.2 R8.1 R15.1 | length 3652.1
  Top Layer w5: v1(2255.91,708.66) 2255.91,692.91 2342.52,606.3 2342.52,271.65 v1(2318.9,248.03)
  MidLayer3 w5: v1(1468.5,248.03) 1484.25,248.03 1496.06,259.84 2291.34,259.84 2303.15,248.03 v1(2318.9,248.03)
  MidLayer4 w5: v2(2255.9,2665.35) 2255.9,2314.96 2311.02,2259.84 2311.02,1850.39 v1(2342.52,1818.9)
  Bottom Layer w5: NT2.2@1441.93,257.87 1458.66,257.87 v1(1468.5,248.03) ; R15.1@2182.59,1307.08 R8.1@2230.78,1307.08 ; v1(2255.91,708.66) 2255.91,1259.84 2230.78,1284.97 R8.1@2230.78,1307.08 ; v1(2342.52,1818.9) 2362.2,1799.21 2362.2,1771.65 2355.26,1764.71 2319.37,1764.71 2306.68,1777.4 2265.46,1777.4 2240.78,1752.72 2240.78,1377.23 2250.44,1367.57 2250.44,1334.89 2242.32,1326.77 2236.22,1326.77 2230.78,1321.33 R8.1@2230.78,1307.08
  Bottom Layer w7.87: HDR_T1.74@2255.91,2606.3 v2(2255.9,2665.35)
FPGA_ID0: HDR_T1.42 NT4.1
FPGA_ID1: HDR_T1.40 NT5.1
FPGA_ID2: HDR_T1.38 NT6.1
FPGA_ID3: HDR_T1.36 NT7.1
FPGA_INIT: HDR_T1.68 R5.1 R18.1 | length 1638.3
  MidLayer4 w5: v2(2161.42,2688.98) 2161.42,2346.46 2291.34,2216.54 2291.34,1838.58 v1(2342.52,1787.4)
  Bottom Layer w5: R18.1@2182.59,1350.39 R5.1@2230.78,1350.39 2230.78,1756.86 2261.32,1787.4 v1(2342.52,1787.4)
  Bottom Layer w7.87: HDR_T1.68@2161.42,2606.3 v2(2161.42,2688.98)
FPGA_INSTALLED: HDR_T1.34 NT1.1 | length 59.1
  Bottom Layer w7.87: HDR_T1.34@1625.99,2606.3 1625.98,2661.42 NT1.1@1625.98,2657.48
FPGA_M0: HDR_T1.60 R13.1 | length 1390.4
  MidLayer4 w5: v2(2035.43,2665.35) 2090.55,2610.24 2090.55,2275.59 2078.74,2263.78 2078.74,2059.06 v2(2098.43,2039.37)
  Bottom Layer w5: HDR_T1.60@2035.43,2606.3 v2(2035.43,2665.35) ; v2(2098.43,2039.37) 2098.42,1885.83 2208.66,1775.59 2208.66,1444.88 2200.78,1437 R13.1@2182.59,1437
FPGA_M1: HDR_T1.58 R12.1 | length 1530.9
  MidLayer4 w5: v2(2003.94,2688.98) 2062.99,2688.98 2106.3,2645.67 2106.3,2275.59 2118.11,2263.78 v2(2118.11,2062.99)
  Bottom Layer w5: HDR_T1.58@2003.94,2606.3 v2(2003.94,2688.98) ; v2(2118.11,2062.99) 2118.11,1885.83 2220.47,1783.46 2220.47,1409.45 2204.72,1393.7 R12.1@2182.59,1393.7
FPGA_M2: HDR_T1.56
FPGA_PROG_CLK: HDR_T1.88 | length 82.7
  Bottom Layer w7.87: HDR_T1.88@2476.38,2606.3 v2(2476.38,2688.98)
FPGA_PROG_PWR_ON: HDR_T1.86
FPGA_PROGRAM: HDR_T1.62 R3.1 R14.1 | length 1655.1
  Bottom Layer w5: R14.1@1015.75,2174.72 R3.1@1066.93,2174.72 R3.1@1059.05,2182.59 ; R3.1@1070.87,2182.59 1070.87,2665.35 1125.98,2720.47 2027.56,2720.47 2066.93,2681.1 HDR_T1.62@2066.93,2606.3
FPGA_TCK: HDR_T1.72 R7.1 | length 1920.6
  Bottom Layer w5: R7.1@862.2,2174.72 862.2,2220.47 1023.62,2381.89 1023.62,2681.1 1110.24,2767.72 2137.8,2767.72 2224.41,2681.1 HDR_T1.72@2224.41,2606.3
FPGA_TDI: HDR_T1.78 R10.1 | length 2062.2
  Bottom Layer w5: R10.1@811.02,2174.72 811.02,2204.72 1011.81,2405.51 1011.81,2685.04 1106.3,2779.53 2232.28,2779.53 2318.9,2692.91 HDR_T1.78@2318.9,2606.3
FPGA_TDO: HDR_T1.54 R4.1 R9.1 | length 1674
  Bottom Layer w5: R4.1@964.56,2072.36 1068.42,2072.36 1090.55,2094.49 1090.55,2192.91 1082.68,2200.79 1082.68,2661.42 1129.92,2708.66 1921.26,2708.66 1940.95,2688.98 HDR_T1.54@1940.95,2606.3
FPGA_TMS: HDR_T1.70 R6.1 | length 1855.8
  Bottom Layer w5: R6.1@913.38,2174.72 913.39,2236.22 1035.43,2358.27 1035.43,2677.17 1114.17,2755.91 2129.92,2755.91 2192.91,2692.91 HDR_T1.70@2192.91,2606.3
